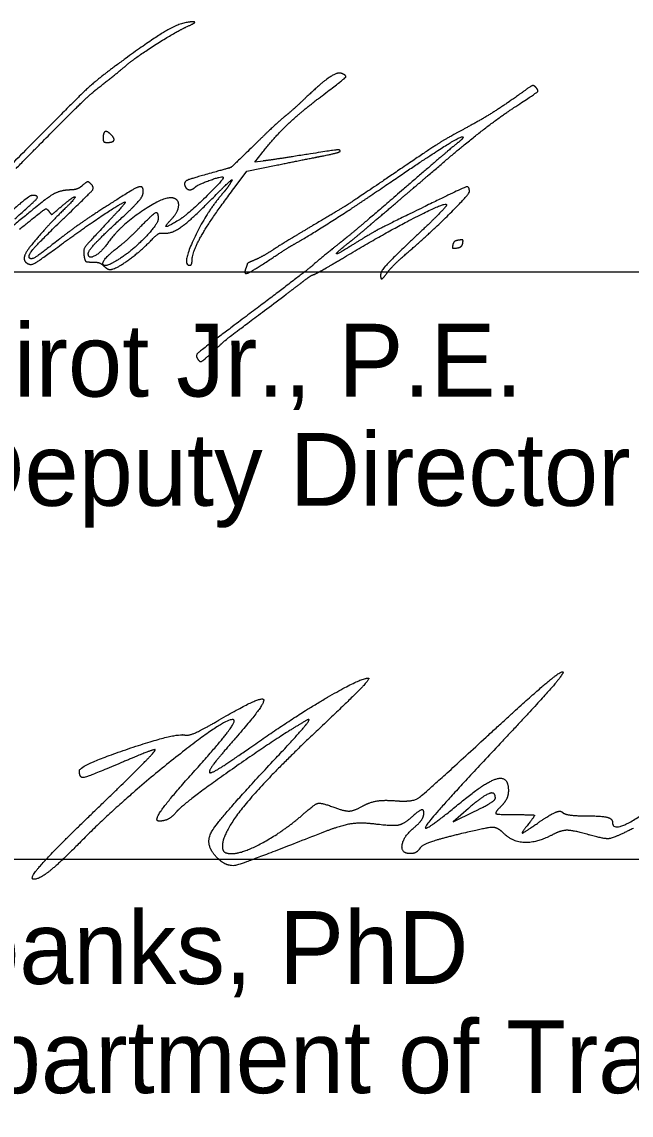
# Model space of a CAD drawing. Extents: x 25.6 to 80.6, y 0.2 to 24.5.
# Drawn here: x 61.107 to 62.278, y 7.535 to 9.637 of the extents above; entities that cross this region are included whole.
import ezdxf

# ---------------------------------------------------------------- set-up
doc = ezdxf.new("R2010")
doc.units = 0
doc.layers.add('SH_Data', color=7, linetype='Continuous')
doc.layers.add('SH_Text', color=7, linetype='Continuous')

msp = doc.modelspace()

# ---------------------------------------------------------------- linework, layer by layer
at = {"layer": 'SH_Data'}
for p, q in [((60.0407, 9.1565), (63.5407, 9.1565)), ((60.0407, 8.0271), (63.5407, 8.0271))]:
    msp.add_line(p, q, dxfattribs=at)
at = {"layer": 'SH_Text'}
for p, q in [((62.0173, 8.1443), (62.0173, 8.1443)), ((61.2401, 8.1132), (61.2401, 8.1132))]:
    msp.add_line(p, q, dxfattribs=at)
for points in [[(61.5707, 9.3695), (61.5547, 9.3675), (61.5687, 9.3853)], [(61.5168, 9.3196), (61.5397, 9.35), (61.5958, 9.3614)], [(61.9655, 8.1246), (61.936, 8.099), (61.9767, 8.1186)]]:
    msp.add_lwpolyline(points, dxfattribs=at)
for points in [[(61.4376, 9.637), (61.4163, 9.6378), (61.3597, 9.6061), (61.2882, 9.5534)], [(61.423, 9.6272), (61.4347, 9.6325), (61.4412, 9.6369), (61.4376, 9.637)], [(61.3101, 9.5555), (61.3274, 9.5702), (61.4026, 9.6179), (61.423, 9.6272)], [(61.2882, 9.5534), (61.2499, 9.5251), (61.2094, 9.4868), (61.0798, 9.3558)], [(61.2479, 9.5055), (61.2702, 9.5229), (61.2972, 9.5446), (61.3101, 9.5555)], [(61.7216, 9.5379), (61.7136, 9.5409), (61.683, 9.5201), (61.6518, 9.4904)], [(61.6841, 9.495), (61.726, 9.5267), (61.7322, 9.5338), (61.7216, 9.5379)], [(61.0958, 9.3552), (61.1683, 9.4293), (61.2368, 9.4969), (61.2479, 9.5055)], [(62.0744, 9.5053), (62.0448, 9.4835), (61.9936, 9.4507), (61.9657, 9.4357)], [(62.053, 9.4721), (62.0959, 9.5003), (62.101, 9.5053), (62.0942, 9.5121)], [(62.0942, 9.5121), (62.091, 9.5153), (62.0854, 9.5134), (62.0744, 9.5053)], [(61.5687, 9.3853), (61.5935, 9.4168), (61.6427, 9.4636), (61.6841, 9.495)], [(61.6518, 9.4904), (61.6384, 9.4775), (61.621, 9.462), (61.6132, 9.4558)], [(61.89, 9.3435), (61.9444, 9.3905), (62.0206, 9.4507), (62.053, 9.4721)], [(61.6132, 9.4558), (61.6053, 9.4496), (61.5788, 9.4248), (61.5541, 9.4008)], [(61.2781, 9.4203), (61.2707, 9.4277), (61.263, 9.4241), (61.263, 9.4131)], [(61.2709, 9.4052), (61.2819, 9.4052), (61.2856, 9.4129), (61.2781, 9.4203)], [(61.9657, 9.4357), (61.9259, 9.4143), (61.8958, 9.3955), (61.8351, 9.3542)], [(61.263, 9.4131), (61.263, 9.408), (61.2658, 9.4052), (61.2709, 9.4052)], [(61.5541, 9.4008), (61.5102, 9.3579), (61.5087, 9.3569), (61.4778, 9.3483)], [(61.774, 9.3005), (61.8802, 9.373), (61.9552, 9.4204), (61.9552, 9.4151)], [(61.944, 9.4037), (61.9379, 9.3989), (61.8989, 9.3657), (61.8574, 9.3299)], [(61.9552, 9.4151), (61.9552, 9.4137), (61.9502, 9.4085), (61.944, 9.4037)], [(61.6295, 9.3782), (61.6059, 9.3745), (61.5795, 9.3706), (61.5707, 9.3695)], [(61.5958, 9.3614), (61.6266, 9.3677), (61.667, 9.3757), (61.6854, 9.3793)], [(61.719, 9.3887), (61.719, 9.3917), (61.7023, 9.3897), (61.6295, 9.3782)], [(61.6854, 9.3793), (61.7039, 9.3829), (61.719, 9.3872), (61.719, 9.3887)], [(61.4939, 9.3385), (61.4968, 9.3357), (61.4261, 9.267), (61.4097, 9.2566)], [(61.4778, 9.3483), (61.4319, 9.3357), (61.4175, 9.329), (61.4203, 9.3217)], [(61.4404, 9.3196), (61.4452, 9.3243), (61.4917, 9.3408), (61.4939, 9.3385)], [(61.8351, 9.3542), (61.7465, 9.294), (61.7273, 9.2817), (61.6681, 9.2465)], [(61.8371, 9.2982), (61.8606, 9.3182), (61.8844, 9.3386), (61.89, 9.3435)], [(61.1988, 9.3138), (61.1781, 9.3133), (61.1467, 9.2923), (61.066, 9.225)], [(61.1946, 9.2662), (61.2367, 9.3067), (61.2461, 9.3176), (61.2423, 9.3222)], [(61.2215, 9.321), (61.2173, 9.3172), (61.2071, 9.3139), (61.1988, 9.3138)], [(61.2423, 9.3222), (61.2361, 9.3296), (61.2307, 9.3293), (61.2215, 9.321)], [(61.3403, 9.3107), (61.3404, 9.32), (61.3297, 9.3203), (61.3155, 9.3115)], [(61.4203, 9.3217), (61.423, 9.3148), (61.4345, 9.3136), (61.4404, 9.3196)], [(61.434, 9.1773), (61.434, 9.1949), (61.4724, 9.2608), (61.5168, 9.3196)], [(61.4806, 9.305), (61.5006, 9.3254), (61.5136, 9.3366), (61.5095, 9.3299)], [(61.5095, 9.3299), (61.5055, 9.3231), (61.4989, 9.314), (61.495, 9.3095)], [(61.8574, 9.3299), (61.7887, 9.2705), (61.735, 9.225), (61.719, 9.2125)], [(61.9674, 9.3111), (61.9674, 9.3219), (61.9535, 9.3171), (61.8789, 9.2807)], [(61.1263, 9.3034), (61.1191, 9.3034), (61.0107, 9.2021), (61.0106, 9.1953)], [(61.0933, 9.2585), (61.1313, 9.2917), (61.1399, 9.3034), (61.1263, 9.3034)], [(61.1778, 9.2779), (61.2041, 9.3007), (61.213, 9.3008), (61.1897, 9.278)], [(61.3155, 9.3115), (61.2596, 9.2766), (61.2064, 9.2407), (61.1798, 9.2199)], [(61.3997, 9.2977), (61.3837, 9.3039), (61.295, 9.2443), (61.2723, 9.2122)], [(61.3018, 9.263), (61.3252, 9.2845), (61.3403, 9.3032), (61.3403, 9.3107)], [(61.3806, 9.2308), (61.3954, 9.2293), (61.4353, 9.2589), (61.4806, 9.305)], [(61.3946, 9.2578), (61.4067, 9.2705), (61.4097, 9.2939), (61.3997, 9.2977)], [(61.495, 9.3095), (61.4617, 9.2716), (61.4138, 9.169), (61.4294, 9.169)], [(61.6274, 9.2079), (61.6501, 9.2205), (61.7381, 9.2761), (61.774, 9.3005)], [(61.7723, 9.2429), (61.7844, 9.2533), (61.8136, 9.2782), (61.8371, 9.2982)], [(61.8513, 9.1959), (61.892, 9.2308), (61.9674, 9.3057), (61.9674, 9.3111)], [(61.1024, 9.2385), (61.1484, 9.2753), (61.1543, 9.2789), (61.1588, 9.2727)], [(61.1897, 9.278), (61.1683, 9.257), (61.1452, 9.232), (61.1257, 9.2086)], [(61.1588, 9.2727), (61.1635, 9.2663), (61.1651, 9.2668), (61.1778, 9.2779)], [(61.183, 9.2094), (61.2268, 9.2417), (61.3037, 9.2926), (61.3057, 9.2906)], [(61.3057, 9.2906), (61.3064, 9.2898), (61.2898, 9.2708), (61.2687, 9.2484)], [(61.7312, 9.1871), (61.8129, 9.2358), (61.9285, 9.2941), (61.923, 9.2838)], [(61.8789, 9.2807), (61.8047, 9.2444), (61.7755, 9.2287), (61.7339, 9.2027)], [(61.923, 9.2838), (61.9207, 9.2795), (61.8949, 9.2535), (61.8657, 9.226)], [(61.1218, 9.1827), (61.1173, 9.1872), (61.1422, 9.2158), (61.1946, 9.2662)], [(61.2345, 9.1913), (61.2345, 9.1969), (61.263, 9.2272), (61.3018, 9.263)], [(61.3689, 9.2584), (61.3689, 9.2489), (61.3224, 9.1999), (61.2981, 9.1837)], [(61.3338, 9.2421), (61.3588, 9.2678), (61.3689, 9.2725), (61.3689, 9.2584)], [(61.4097, 9.2566), (61.3882, 9.2431), (61.381, 9.2436), (61.3946, 9.2578)], [(61.2687, 9.2484), (61.2311, 9.2085), (61.2242, 9.1976), (61.2271, 9.1826)], [(61.2905, 9.2026), (61.3011, 9.2107), (61.3206, 9.2285), (61.3338, 9.2421)], [(61.3521, 9.2137), (61.3656, 9.2275), (61.3725, 9.2317), (61.3806, 9.2308)], [(61.6681, 9.2465), (61.6368, 9.2279), (61.6015, 9.2064), (61.5898, 9.1988)], [(61.7325, 9.2102), (61.7423, 9.2178), (61.7602, 9.2325), (61.7723, 9.2429)], [(61.1257, 9.2086), (61.1139, 9.1944), (61.1096, 9.1774), (61.1167, 9.173)], [(61.1167, 9.173), (61.1239, 9.1685), (61.1383, 9.1764), (61.183, 9.2094)], [(61.1798, 9.2199), (61.1419, 9.1903), (61.125, 9.1795), (61.1218, 9.1827)], [(61.2723, 9.2122), (61.2595, 9.1939), (61.2345, 9.1802), (61.2345, 9.1913)], [(61.2768, 9.1609), (61.2858, 9.1609), (61.3326, 9.1937), (61.3521, 9.2137)], [(61.5839, 9.1801), (61.6033, 9.193), (61.6229, 9.2055), (61.6274, 9.2079)], [(61.719, 9.2125), (61.7066, 9.2029), (61.6681, 9.1711), (61.6661, 9.1689)], [(61.7339, 9.2027), (61.7121, 9.189), (61.7112, 9.1936), (61.7325, 9.2102)], [(61.8657, 9.226), (61.8144, 9.1777), (61.7941, 9.1535), (61.7972, 9.1443)], [(61.9355, 9.2084), (61.9344, 9.2026), (61.9362, 9.2013), (61.9436, 9.2023)], [(61.9464, 9.2172), (61.9411, 9.2165), (61.9363, 9.2126), (61.9355, 9.2084)], [(61.9436, 9.2023), (61.9488, 9.2031), (61.9537, 9.207), (61.9545, 9.2111)], [(61.9545, 9.2111), (61.9556, 9.2169), (61.9538, 9.2183), (61.9464, 9.2172)], [(61.2981, 9.1837), (61.2663, 9.1625), (61.2597, 9.1789), (61.2905, 9.2026)], [(61.5898, 9.1988), (61.5781, 9.1912), (61.562, 9.1823), (61.5542, 9.179)], [(61.668, 9.1512), (61.6703, 9.1516), (61.6988, 9.1677), (61.7312, 9.1871)], [(61.8087, 9.1538), (61.8142, 9.1615), (61.8334, 9.1805), (61.8513, 9.1959)], [(61.2271, 9.1826), (61.2282, 9.1771), (61.2323, 9.1752), (61.2427, 9.1752)], [(61.2427, 9.1752), (61.2508, 9.1753), (61.2598, 9.1723), (61.2639, 9.1681)], [(61.2639, 9.1681), (61.2679, 9.1641), (61.2737, 9.1609), (61.2768, 9.1609)], [(61.4294, 9.169), (61.432, 9.169), (61.434, 9.1728), (61.434, 9.1773)], [(61.6661, 9.1689), (61.6638, 9.1664), (61.5816, 9.1035), (61.5114, 9.0507)], [(61.5374, 9.1633), (61.5327, 9.151), (61.5481, 9.1566), (61.5839, 9.1801)], [(61.5399, 9.1714), (61.5399, 9.1705), (61.5388, 9.1668), (61.5374, 9.1633)], [(61.5542, 9.179), (61.5463, 9.1757), (61.5399, 9.1723), (61.5399, 9.1714)], [(61.6497, 9.1396), (61.6575, 9.1456), (61.6658, 9.1508), (61.668, 9.1512)], [(61.7972, 9.1443), (61.798, 9.1418), (61.8032, 9.1461), (61.8087, 9.1538)], [(61.6152, 9.1134), (61.6264, 9.1218), (61.6419, 9.1336), (61.6497, 9.1396)], [(61.4744, 9.0031), (61.499, 9.0258), (61.5065, 9.0317), (61.6152, 9.1134)], [(61.5114, 9.0507), (61.4509, 9.0051), (61.4405, 8.9958), (61.4439, 8.9903)], [(61.4439, 8.9903), (61.4487, 8.9826), (61.4549, 8.9852), (61.4744, 9.0031)], [(61.5454, 8.2413), (61.6259, 8.298), (61.7573, 8.3752), (61.773, 8.3752)], [(61.773, 8.3752), (61.7778, 8.3752), (61.7365, 8.3326), (61.6812, 8.2805)], [(61.9997, 8.2618), (62.0747, 8.3309), (62.1407, 8.3875), (62.1464, 8.3875)], [(62.1464, 8.3875), (62.1522, 8.3876), (62.1001, 8.3275), (62.0308, 8.2539)], [(61.4864, 8.2948), (61.5652, 8.341), (61.5774, 8.3278), (61.5182, 8.2605)], [(61.5145, 8.2946), (61.5049, 8.3042), (61.2952, 8.1373), (61.2173, 8.058)], [(61.6548, 8.2942), (61.6057, 8.2664), (61.4174, 8.1341), (61.4042, 8.1182)], [(61.4208, 8.2656), (61.4264, 8.2638), (61.4559, 8.277), (61.4864, 8.2948)], [(61.4367, 8.1942), (61.483, 8.246), (61.518, 8.2911), (61.5145, 8.2946)], [(61.5896, 8.2152), (61.6358, 8.2645), (61.6651, 8.3), (61.6548, 8.2942)], [(61.2175, 8.1971), (61.2177, 8.2076), (61.4051, 8.2708), (61.4208, 8.2656)], [(61.6812, 8.2805), (61.5815, 8.1868), (61.4923, 8.0786), (61.4923, 8.0516)], [(61.8247, 8.1394), (61.8582, 8.1366), (61.8816, 8.153), (61.9997, 8.2618)], [(61.5182, 8.2605), (61.4902, 8.2286), (61.4673, 8.199), (61.4673, 8.1945)], [(61.4673, 8.1945), (61.4673, 8.1901), (61.5024, 8.2111), (61.5454, 8.2413)], [(62.0308, 8.2539), (61.9013, 8.1163), (61.8692, 8.0691), (61.9514, 8.1368)], [(61.2401, 8.1132), (61.3111, 8.1817), (61.3665, 8.2377), (61.363, 8.2377)], [(61.363, 8.2377), (61.3596, 8.2377), (61.3306, 8.2264), (61.2985, 8.2127)], [(61.2985, 8.2127), (61.2359, 8.1859), (61.2172, 8.1822), (61.2175, 8.1971)], [(61.4825, 8.0296), (61.4573, 8.0548), (61.4862, 8.1049), (61.5896, 8.2152)], [(62.2423, 8.0987), (62.2423, 8.0759), (62.3376, 8.1373), (62.4079, 8.2055)], [(61.3709, 8.1002), (61.3606, 8.1002), (61.3895, 8.1415), (61.4367, 8.1942)], [(61.9514, 8.1368), (61.9998, 8.1767), (62.0423, 8.187), (62.0423, 8.1589)], [(62.0423, 8.1589), (62.0423, 8.15), (62.0355, 8.1359), (62.0273, 8.1277)], [(61.7617, 8.1289), (61.7751, 8.1365), (61.8034, 8.1412), (61.8247, 8.1394)], [(62.0173, 8.1443), (62.0173, 8.1577), (61.9932, 8.1486), (61.9655, 8.1246)], [(61.9767, 8.1186), (61.999, 8.1295), (62.0173, 8.141), (62.0173, 8.1443)], [(61.4042, 8.1182), (61.3959, 8.1083), (61.381, 8.1002), (61.3709, 8.1002)], [(61.5103, 8.0377), (61.532, 8.0377), (61.6134, 8.0829), (61.6498, 8.1152)], [(61.6498, 8.1152), (61.6701, 8.1332), (61.6829, 8.1359), (61.7067, 8.1268)], [(61.7067, 8.1268), (61.7269, 8.1192), (61.7457, 8.1199), (61.7617, 8.1289)], [(61.8798, 8.1162), (61.8798, 8.1233), (61.8696, 8.1199), (61.8572, 8.1086)], [(61.861, 8.0877), (61.8713, 8.0963), (61.8798, 8.1091), (61.8798, 8.1162)], [(62.0273, 8.1277), (62.0156, 8.116), (62.0215, 8.1127), (62.0538, 8.1127)], [(62.0999, 8.0972), (62.1213, 8.1122), (62.1421, 8.1212), (62.146, 8.1173)], [(62.146, 8.1173), (62.1499, 8.1134), (62.1732, 8.1102), (62.1977, 8.1102)], [(61.1298, 7.9884), (61.1195, 7.9886), (61.1691, 8.0448), (61.2401, 8.1132)], [(61.7877, 8.0942), (61.7585, 8.098), (61.7186, 8.0915), (61.6821, 8.0771)], [(61.8572, 8.1086), (61.8415, 8.0945), (61.8203, 8.0901), (61.7877, 8.0942)], [(62.0538, 8.1127), (62.0913, 8.1127), (62.0937, 8.1106), (62.0782, 8.0913)], [(62.0782, 8.0913), (62.0662, 8.0763), (62.0726, 8.0781), (62.0999, 8.0972)], [(62.1977, 8.1102), (62.2222, 8.1102), (62.2423, 8.105), (62.2423, 8.0987)], [(61.6821, 8.0771), (61.5361, 8.0194), (61.501, 8.0111), (61.4825, 8.0296)], [(61.854, 8.0377), (61.8357, 8.0377), (61.8402, 8.0704), (61.861, 8.0877)], [(61.9483, 8.0752), (61.91, 8.0659), (61.8757, 8.0538), (61.8722, 8.0481)], [(62.0327, 8.0773), (62.0216, 8.0884), (62.0015, 8.0879), (61.9483, 8.0752)], [(62.129, 8.0748), (62.0982, 8.0583), (62.0504, 8.0596), (62.0327, 8.0773)], [(62.1935, 8.0748), (62.1666, 8.0826), (62.1435, 8.0825), (62.129, 8.0748)], [(62.2826, 8.0862), (62.2452, 8.0677), (62.2266, 8.0653), (62.1935, 8.0748)], [(61.2173, 8.058), (61.1795, 8.0195), (61.1401, 7.9882), (61.1298, 7.9884)], [(61.4923, 8.0516), (61.4923, 8.044), (61.5004, 8.0377), (61.5103, 8.0377)], [(61.8722, 8.0481), (61.8687, 8.0424), (61.8605, 8.0377), (61.854, 8.0377)]]:
    msp.add_open_spline(points, degree=2, dxfattribs=at)

# ---------------------------------------------------------------- texts
for s, p in [('Arthur G. Noirot Jr., P.E.', (60.0407, 8.9165)), ('District       Deputy Director', (60.0407, 8.7065)), ('Jack Marchbanks, PhD', (60.0407, 7.7871)), ('Director, Department of Transportation', (60.0407, 7.5771))]:
    msp.add_text(s, height=0.14, dxfattribs=at).set_placement(p)

doc.saveas('drawing.dxf')
